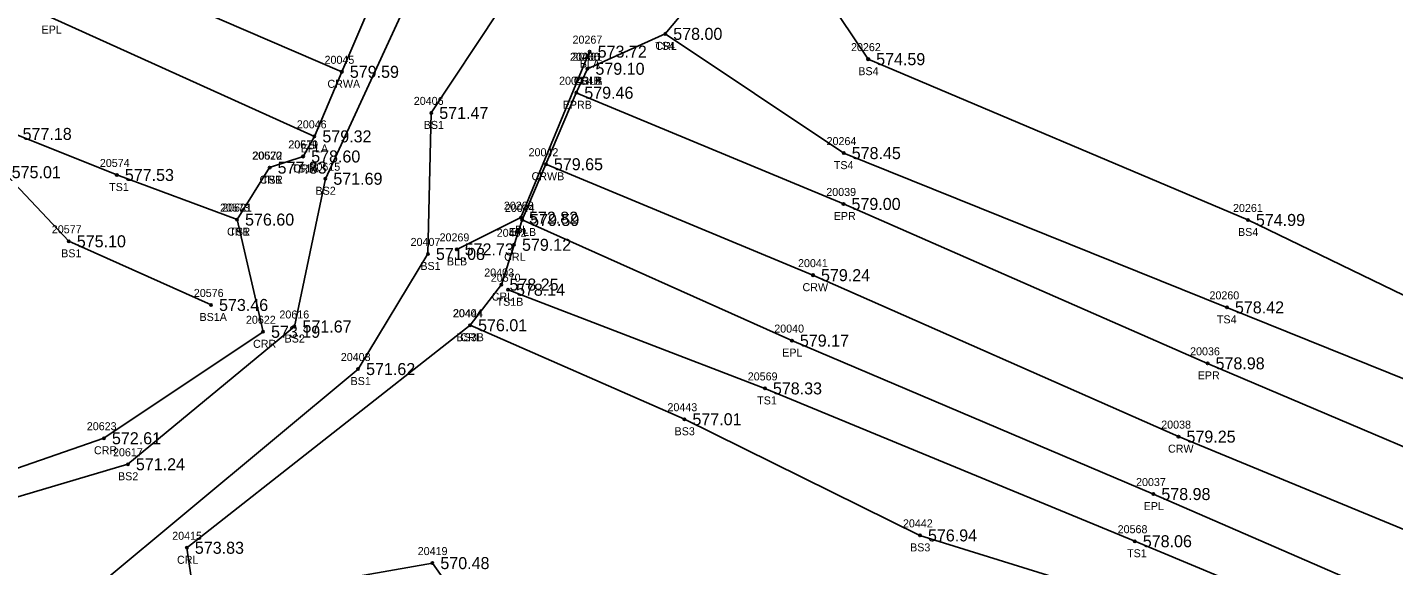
# Model space of a CAD drawing. Extents: x 1664837 to 1666270, y 987403 to 988245.
# Drawn here: x 1665462.9 to 1665633.6, y 987705.8 to 987773 of the extents above; entities that cross this region are included whole.
import ezdxf

# ---------------------------------------------------------------- set-up
doc = ezdxf.new("R2010")
doc.units = 0
for name, color, linetype in [('RD_DTM_BkLn1', 7, 'Continuous'), ('RD_DTM_BkLn2', 7, 'Continuous'), ('RD_DTM_BkLn_txCode', 7, 'Continuous'), ('RD_EX_H2O', 7, 'Continuous'), ('RD_EX_H2O_txCode', 7, 'Continuous'), ('RD_EX_Road', 7, 'Continuous'), ('RD_EX_Road_txCode', 7, 'Continuous'), ('RD_EX_TX_H2O_ELEV', 7, 'Continuous'), ('RD_EX_TX_Misc_ELEV', 7, 'Continuous'), ('RD_EX_TX_Road_ELEV', 7, 'Continuous'), ('RD_HC_Survey_ELEV', 7, 'Continuous'), ('RD_HC_Survey_txCode', 7, 'Continuous'), ('RD_SMD_Locator', 7, 'Continuous')]:
    doc.layers.add(name, color=color, linetype=linetype)

msp = doc.modelspace()

# ---------------------------------------------------------------- linework, layer by layer
at = {"layer": 'RD_DTM_BkLn1'}
for points in [[(1665502.18, 987767.43), (1665469.18, 987781.68), (1665423.29, 987801.23), (1665377.17, 987820.37), (1665331.28, 987839.54), (1665285.44, 987859.03), (1665239.3, 987878.58), (1665193.14, 987897.86), (1665147.41, 987917.57), (1665101.07, 987936.7), (1665055.19, 987956.08), (1665009.23, 987975.83), (1664963.42, 987995.66), (1664917.15, 988015.07), (1664871.41, 988034.69)], [(1665533.14, 987769.95), (1665524.56, 987749.22), (1665516.53, 987745.26)], [(1666158.65, 987488.74), (1666112.69, 987508.17), (1666066.71, 987527.94), (1666020.54, 987547.08), (1665974.85, 987566.77), (1665928.96, 987586.52), (1665882.66, 987605.79), (1665836.76, 987625.38), (1665790.86, 987644.81), (1665744.75, 987663.93), (1665698.8, 987683.39), (1665652.93, 987702.82), (1665606.7, 987721.88), (1665561.04, 987742.04), (1665527.67, 987755.89)]]:
    msp.add_lwpolyline(points, dxfattribs=at)
at = {"layer": 'RD_DTM_BkLn2'}
for points in [[(1665497.35, 987756.86), (1665493.15, 987755.47), (1665489.09, 987748.98), (1665474.07, 987754.55), (1665461.3, 987759.68), (1665416.12, 987784.47), (1665369.46, 987807.94), (1665325.7, 987826.1), (1665279.41, 987845.24), (1665231.91, 987860.98), (1665183.47, 987888.09), (1665142.67, 987907.67), (1665119.08, 987916.32), (1665106.25, 987916.18)], [(1665485.84, 987738.32), (1665468.07, 987746.27), (1665459.94, 987754.9), (1665412.19, 987777.99), (1665366.38, 987802.17), (1665323.99, 987821.27), (1665274.79, 987834.22), (1665225.63, 987853.6), (1665180.43, 987876.62), (1665166.98, 987883.63), (1665152.71, 987895.52), (1665118.68, 987912.3), (1665108.44, 987911.82), (1665107.08, 987900.15)], [(1665937.25, 987616.34), (1665889.99, 987630.17), (1665844.42, 987647.08), (1665801.11, 987667.84), (1665753.91, 987686.95), (1665707.93, 987709.21), (1665661.99, 987726.38), (1665615.37, 987748.93), (1665567.93, 987769.01), (1665555.48, 987787.59)], [(1665511.23, 987778.14), (1665500.12, 987754.08), (1665496.26, 987735.63), (1665475.45, 987718.43), (1665445.39, 987709.52), (1665428.04, 987704.31), (1665389.45, 987688.17), (1665361.39, 987673.13), (1665330.12, 987656.7), (1665283.57, 987647.17), (1665235.53, 987667.53), (1665208.93, 987663.65), (1665168.4, 987630.38), (1665122.54, 987622.98), (1665093.74, 987624.1), (1665049.09, 987603.27)], [(1665521.8, 987775.03), (1665513.35, 987762.3), (1665512.93, 987744.69), (1665504.21, 987730.32), (1665472.11, 987703.59), (1665484.52, 987698.45), (1665513.21, 987703.54), (1665525.98, 987684.44), (1665562.43, 987664.02), (1665594.02, 987677.42), (1665619.36, 987684.18), (1665641.6, 987678.85), (1665662.25, 987650.14), (1665684.59, 987631.79), (1665704.75, 987626.25), (1665722.78, 987589.94)], [(1665936.46, 987601.23), (1665888.67, 987621.23), (1665842.7, 987640.33), (1665797.93, 987660.83), (1665752.01, 987681.29), (1665704.64, 987700.49), (1665658.36, 987719.6), (1665612.75, 987738.02), (1665564.88, 987757.28), (1665542.58, 987772.17), (1665532.86, 987767.81)], [(1666152.82, 987476.83), (1666108.53, 987496.54), (1666062.68, 987516.61), (1666015.91, 987535.8), (1665969.55, 987555.16), (1665926.09, 987572.12), (1665875.73, 987592.3), (1665829.7, 987613.88), (1665783.86, 987631.56), (1665738.66, 987650.04), (1665693.22, 987670.26), (1665645.99, 987690.14), (1665601.24, 987708.82), (1665555.03, 987727.9), (1665522.94, 987740.22)], [(1665619.37, 987685.12), (1665609.35, 987698.68), (1665574.4, 987709.55), (1665544.98, 987724.05), (1665518.2, 987735.79)]]:
    msp.add_lwpolyline(points, dxfattribs=at)
at = {"layer": 'RD_EX_H2O'}
for points in [[(1665565.69, 987792.78), (1665555.48, 987787.59), (1665542.58, 987772.17), (1665532.86, 987767.81), (1665532.86, 987767.81), (1665531.47, 987764.82)], [(1665498.75, 987759.37), (1665497.35, 987756.86), (1665493.15, 987755.47), (1665489.09, 987748.98), (1665492.34, 987734.97), (1665472.46, 987721.68), (1665444.71, 987712.07), (1665426.39, 987705.52), (1665387.14, 987692.07), (1665353.81, 987678.17), (1665328.18, 987659.89), (1665283.87, 987652.21), (1665224.39, 987676.29), (1665206.47, 987666.98), (1665167.33, 987633.9), (1665123.23, 987629.54), (1665093.05, 987625.54), (1665046.91, 987607.08)], [(1665524.71, 987748.93), (1665523.69, 987745.83), (1665522.12, 987740.87), (1665518.2, 987735.79), (1665482.82, 987708), (1665483.87, 987700.87), (1665513.49, 987706.09), (1665528.04, 987685.52), (1665561.97, 987665.98), (1665593.48, 987679.22), (1665619.37, 987685.12), (1665642.78, 987680.31), (1665663.97, 987651.85), (1665686.03, 987634.26), (1665705.62, 987627.98), (1665724.83, 987594.97)]]:
    msp.add_lwpolyline(points, dxfattribs=at)
at = {"layer": 'RD_EX_Road'}
for points in [[(1665498.75, 987759.37), (1665465.87, 987774.2), (1665419.78, 987793.88), (1665373.62, 987813.14), (1665327.95, 987832.31), (1665281.42, 987852.3), (1665236.13, 987871.34), (1665189.6, 987890.71), (1665143.92, 987909.97), (1665117.43, 987920.99), (1665086.22, 987934.27), (1665051.62, 987948.55), (1665005.38, 987968.44), (1664960.17, 987987.67), (1664913.53, 988007.62), (1664868.21, 988026.81)], [(1665506.06, 987776.52), (1665502.18, 987767.43), (1665498.75, 987759.37)], [(1665524.71, 987748.93), (1665527.67, 987755.89), (1665531.47, 987764.82)], [(1666163.18, 987497.62), (1666116.6, 987517.39), (1666070.7, 987536.94), (1666024.42, 987556.43), (1665979.02, 987575.67), (1665932.35, 987595.55), (1665886.93, 987614.54), (1665839.87, 987634.25), (1665794.5, 987653.27), (1665748.81, 987672.51), (1665702.36, 987691.87), (1665656.42, 987711.45), (1665610.33, 987731.03), (1665564.85, 987750.93), (1665531.47, 987764.82)], [(1666156.67, 987480.61), (1666109.28, 987500.74), (1666063.55, 987520.04), (1666017.04, 987539.82), (1665971.11, 987559.14), (1665924.88, 987578.79), (1665879.5, 987597.89), (1665833.22, 987617.38), (1665786.91, 987636.81), (1665741.44, 987656.13), (1665695.81, 987675.2), (1665649.26, 987694.85), (1665603.56, 987714.71), (1665558.4, 987733.87), (1665524.71, 987748.93)]]:
    msp.add_lwpolyline(points, dxfattribs=at)
at = {"layer": 'RD_SMD_Locator'}
for centre in [(1665542.58, 987772.17), (1665542.58, 987772.17), (1665533.14, 987769.95), (1665567.93, 987769.01), (1665502.18, 987767.43), (1665532.86, 987767.81), (1665532.86, 987767.81), (1665532.86, 987767.81), (1665531.47, 987764.82), (1665513.35, 987762.3), (1665498.75, 987759.37), (1665497.35, 987756.86), (1665497.35, 987756.86), (1665564.88, 987757.28), (1665474.07, 987754.55), (1665493.15, 987755.47), (1665493.15, 987755.47), (1665527.67, 987755.89), (1665500.12, 987754.08), (1665564.85, 987750.93), (1665489.09, 987748.98), (1665489.09, 987748.98), (1665524.56, 987749.22), (1665524.71, 987748.93), (1665615.37, 987748.93), (1665468.07, 987746.27), (1665512.93, 987744.69), (1665516.53, 987745.26), (1665523.69, 987745.83), (1665522.12, 987740.87), (1665561.04, 987742.04), (1665522.94, 987740.22), (1665485.84, 987738.32), (1665612.75, 987738.02), (1665518.2, 987735.79), (1665518.2, 987735.79), (1665492.34, 987734.97), (1665496.26, 987735.63), (1665558.4, 987733.87), (1665610.33, 987731.03), (1665504.21, 987730.32), (1665555.03, 987727.9), (1665544.98, 987724.05), (1665472.46, 987721.68), (1665606.7, 987721.88), (1665475.45, 987718.43), (1665603.56, 987714.71), (1665574.4, 987709.55), (1665601.24, 987708.82), (1665482.82, 987708), (1665513.49, 987706.09)]:
    msp.add_circle(centre, 0.15, dxfattribs=at)

# ---------------------------------------------------------------- texts
at = {"layer": 'RD_DTM_BkLn_txCode'}
for s, p in [('20267', (1665531, 987770.95)), ('TS4', (1665541.33, 987770.17)), ('20262', (1665565.79, 987770.01)), ('20266', (1665530.7, 987768.81)), ('BLA', (1665531.9, 987767.95)), ('TS4B', (1665531.15, 987765.81)), ('BS4', (1665566.7, 987767.01)), ('20406', (1665511.17, 987763.3)), ('BS1', (1665512.41, 987760.3)), ('20571', (1665495.51, 987757.86)), ('20264', (1665562.74, 987758.28)), ('20574', (1665471.95, 987755.55)), ('20572', (1665491.03, 987756.47)), ('TS1A', (1665495.9, 987754.86)), ('20615', (1665498.26, 987755.08)), ('TS4', (1665563.64, 987755.28)), ('TS1', (1665473.11, 987752.55)), ('TS1', (1665492.19, 987753.47)), ('BS2', (1665498.89, 987752.08)), ('20268', (1665522.42, 987750.22)), ('20573', (1665486.97, 987749.98)), ('20261', (1665613.51, 987749.93)), ('20577', (1665465.95, 987747.27)), ('TS1', (1665488.13, 987746.98)), ('BL', (1665523.81, 987747.22)), ('BS4', (1665614.14, 987746.93)), ('20407', (1665510.77, 987745.69)), ('20269', (1665514.39, 987746.26)), ('BS1', (1665467.12, 987744.27)), ('BS1', (1665511.99, 987742.69)), ('BLB', (1665515.31, 987743.26)), ('20570', (1665520.79, 987741.22)), ('20576', (1665483.69, 987739.32)), ('20260', (1665610.57, 987739.02)), ('20616', (1665494.38, 987736.63)), ('20444', (1665516.08, 987736.79)), ('TS1B', (1665521.51, 987738.22)), ('BS1A', (1665484.4, 987736.32)), ('TS4', (1665611.5, 987736.02)), ('BS2', (1665495.03, 987733.63)), ('BS3B', (1665516.5, 987733.79)), ('20408', (1665502.05, 987731.32)), ('BS1', (1665503.27, 987728.32)), ('20569', (1665552.89, 987728.9)), ('20443', (1665542.86, 987725.05)), ('TS1', (1665554.07, 987725.9)), ('BS3', (1665543.75, 987722.05)), ('20617', (1665473.59, 987719.43)), ('BS2', (1665474.22, 987716.43)), ('20442', (1665572.28, 987710.55)), ('20568', (1665599.1, 987709.82)), ('BS3', (1665573.17, 987707.55)), ('TS1', (1665600.28, 987706.82))]:
    msp.add_text(s, height=1, dxfattribs=at).set_placement(p)
at = {"layer": 'RD_EX_H2O_txCode'}
for s, p in [('CRL', (1665541.35, 987770.17)), ('20400', (1665530.67, 987768.81)), ('20401', (1665530.99, 987768.81)), ('CRLA', (1665531.15, 987765.81)), ('CRLB', (1665531.16, 987765.81)), ('20619', (1665495.49, 987757.86)), ('20620', (1665490.97, 987756.47)), ('CRR', (1665496.1, 987754.86)), ('CRR', (1665491.9, 987753.47)), ('20621', (1665487.23, 987749.98)), ('CRR', (1665487.84, 987746.98)), ('20402', (1665521.53, 987746.83)), ('CRL', (1665522.46, 987743.83)), ('20403', (1665519.97, 987741.87)), ('CRL', (1665520.89, 987738.87)), ('20404', (1665516.04, 987736.79)), ('20622', (1665490.2, 987735.97)), ('CRL', (1665516.97, 987733.79)), ('CRR', (1665491.09, 987732.97)), ('20623', (1665470.32, 987722.68)), ('CRR', (1665471.21, 987719.68)), ('20415', (1665480.99, 987709)), ('CRL', (1665481.59, 987706)), ('20419', (1665511.66, 987707.09))]:
    msp.add_text(s, height=1, dxfattribs=at).set_placement(p)
at = {"layer": 'RD_EX_Road_txCode'}
for s, p in [('EPL', (1665464.67, 987772.2)), ('20043', (1665529.32, 987765.82)), ('EPRB', (1665529.77, 987762.82)), ('20046', (1665496.56, 987760.37)), ('EPLA', (1665497.05, 987757.37)), ('20039', (1665562.7, 987751.93)), ('20044', (1665522.55, 987749.93)), ('EPR', (1665563.63, 987748.93)), ('EPLB', (1665523.03, 987746.93)), ('20040', (1665556.2, 987734.87)), ('EPL', (1665557.2, 987731.87)), ('20036', (1665608.15, 987732.03)), ('EPR', (1665609.1, 987729.03)), ('20037', (1665601.4, 987715.71)), ('EPL', (1665602.35, 987712.71))]:
    msp.add_text(s, height=1, dxfattribs=at).set_placement(p)
at = {"layer": 'RD_EX_TX_H2O_ELEV'}
for s, p in [('578.00', (1665543.58, 987771.42)), ('579.10', (1665533.86, 987767.06)), ('579.10', (1665533.86, 987767.06)), ('578.60', (1665498.35, 987756.11)), ('577.83', (1665494.15, 987754.72)), ('576.60', (1665490.09, 987748.23)), ('579.12', (1665524.69, 987745.08)), ('578.25', (1665523.12, 987740.12)), ('576.01', (1665519.2, 987735.04)), ('573.19', (1665493.34, 987734.22)), ('572.61', (1665473.46, 987720.93)), ('573.83', (1665483.82, 987707.25)), ('570.48', (1665514.49, 987705.34))]:
    msp.add_text(s, height=1.5, dxfattribs=at).set_placement(p)
at = {"layer": 'RD_EX_TX_Misc_ELEV'}
for s, p in [('578.00', (1665543.58, 987771.42)), ('573.72', (1665534.14, 987769.2)), ('579.10', (1665533.86, 987767.06)), ('574.59', (1665568.93, 987768.26)), ('571.47', (1665514.35, 987761.55)), ('577.18', (1665462.3, 987758.93)), ('578.60', (1665498.35, 987756.11)), ('578.45', (1665565.88, 987756.53)), ('575.01', (1665460.94, 987754.15)), ('577.53', (1665475.07, 987753.8)), ('577.83', (1665494.15, 987754.72)), ('571.69', (1665501.12, 987753.33)), ('576.60', (1665490.09, 987748.23)), ('572.82', (1665525.56, 987748.47)), ('574.99', (1665616.37, 987748.18)), ('575.10', (1665469.07, 987745.52)), ('571.08', (1665513.93, 987743.94)), ('572.73', (1665517.53, 987744.51)), ('578.14', (1665523.94, 987739.47)), ('573.46', (1665486.84, 987737.57)), ('578.42', (1665613.75, 987737.27)), ('571.67', (1665497.26, 987734.88)), ('576.01', (1665519.2, 987735.04)), ('571.62', (1665505.21, 987729.57)), ('578.33', (1665556.03, 987727.15)), ('577.01', (1665545.98, 987723.3)), ('571.24', (1665476.45, 987717.68)), ('576.94', (1665575.4, 987708.8)), ('578.06', (1665602.24, 987708.07))]:
    msp.add_text(s, height=1.5, dxfattribs=at).set_placement(p)
at = {"layer": 'RD_EX_TX_Road_ELEV'}
for s, p in [('579.46', (1665532.47, 987764.07)), ('579.32', (1665499.75, 987758.62)), ('579.00', (1665565.85, 987750.18)), ('579.59', (1665525.71, 987748.18)), ('579.17', (1665559.4, 987733.12)), ('578.98', (1665611.33, 987730.28)), ('578.98', (1665604.56, 987713.96))]:
    msp.add_text(s, height=1.5, dxfattribs=at).set_placement(p)
at = {"layer": 'RD_HC_Survey_ELEV'}
for s, p in [('579.59', (1665503.18, 987766.68)), ('579.65', (1665528.67, 987755.14)), ('579.24', (1665562.04, 987741.29)), ('579.25', (1665607.7, 987721.13))]:
    msp.add_text(s, height=1.5, dxfattribs=at).set_placement(p)
at = {"layer": 'RD_HC_Survey_txCode'}
for s, p in [('20045', (1665500.02, 987768.43)), ('CRWA', (1665500.38, 987765.43)), ('20042', (1665525.51, 987756.89)), ('CRWB', (1665525.88, 987753.89)), ('20041', (1665559.17, 987743.04)), ('CRW', (1665559.73, 987740.04)), ('20038', (1665604.54, 987722.88)), ('CRW', (1665605.39, 987719.88))]:
    msp.add_text(s, height=1, dxfattribs=at).set_placement(p)

doc.saveas('drawing.dxf')
